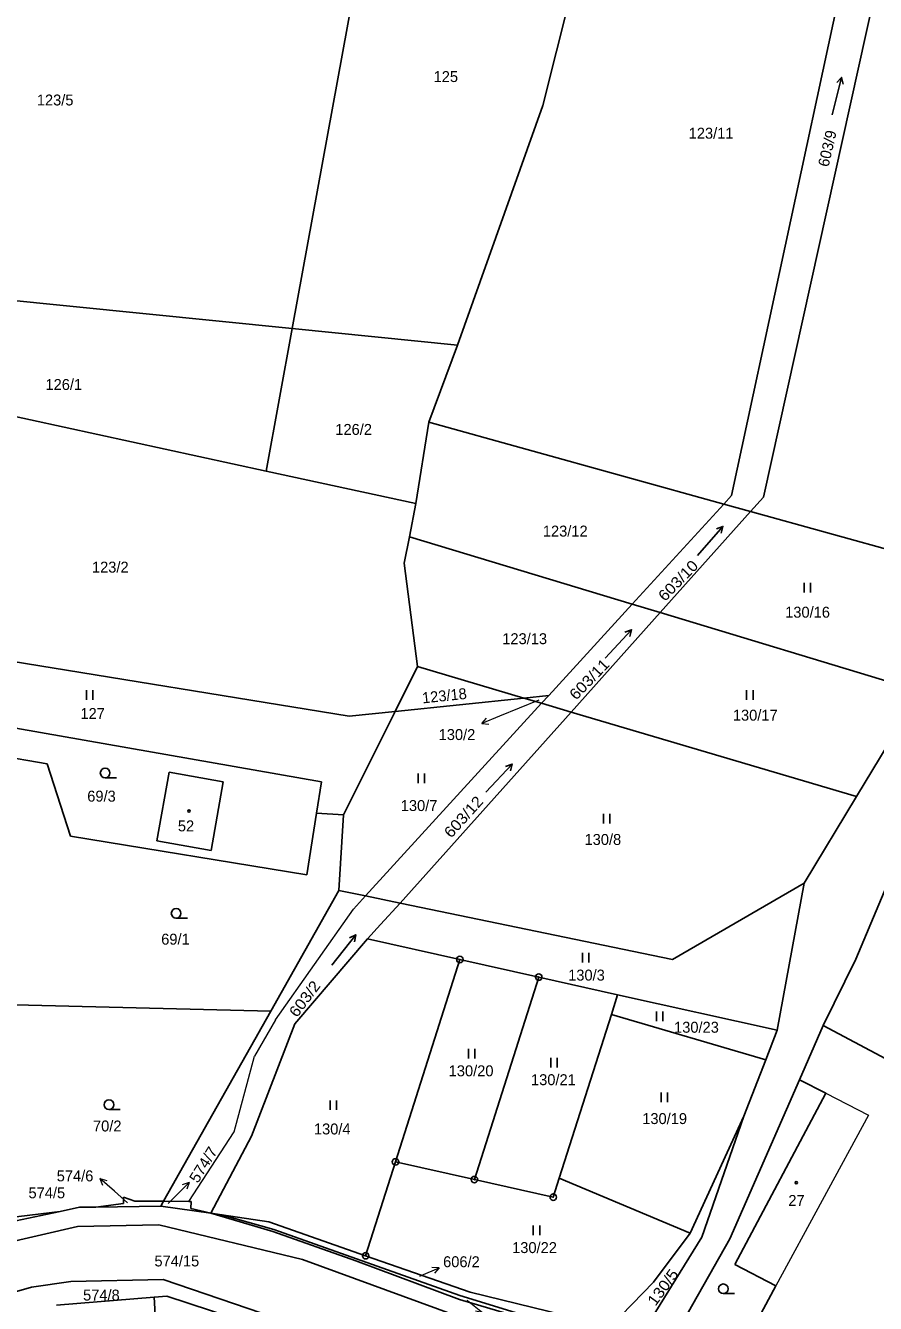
# Model space of a CAD drawing. Extents: x -664548 to -662415, y -1069720 to -1068208.
# Drawn here: x -663625.9 to -663493.9, y -1068905.8 to -1068707.2 of the extents above; entities that cross this region are included whole.
import ezdxf
from ezdxf.enums import TextEntityAlignment as Align

# ---------------------------------------------------------------- set-up
doc = ezdxf.new("R2010")
doc.units = 0
doc.header["$LTSCALE"] = 0.68
for name, color, linetype, lineweight in [('1', 7, 'Continuous', 25), ('3', 7, 'Continuous', 25), ('4', 7, 'Continuous', 13), ('5', 7, 'Continuous', 25), ('7', 7, 'Continuous', 13), ('8', 7, 'Continuous', 25)]:
    doc.layers.add(name, color=color, linetype=linetype, lineweight=lineweight)
doc.layers.add('2', color=7, linetype='Continuous')

msp = doc.modelspace()

# ---------------------------------------------------------------- linework, layer by layer
at = {"layer": '1'}
for p, q in [((-663545.54, -1068719.64), (-663534.68, -1068676.07)), ((-663574.64, -1068700.41), (-663584.45, -1068754.3)), ((-663516.25, -1068780.25), (-663499.18, -1068700.75)), ((-663511.29, -1068780.48), (-663493.94, -1068701.92)), ((-663558.79, -1068756.87), (-663545.54, -1068719.64)), ((-663661.19, -1068746.6), (-663584.45, -1068754.3)), ((-663584.45, -1068754.3), (-663588.49, -1068776.46)), ((-663584.45, -1068754.3), (-663558.79, -1068756.87)), ((-663563.23, -1068768.86), (-663558.79, -1068756.87)), ((-663652.43, -1068762.58), (-663588.49, -1068776.46)), ((-663565.25, -1068781.51), (-663563.23, -1068768.86)), ((-663517.45, -1068781.57), (-663563.23, -1068768.86)), ((-663588.49, -1068776.46), (-663565.25, -1068781.51)), ((-663565.25, -1068781.51), (-663566.26, -1068786.68)), ((-663531.67, -1068797.14), (-663517.45, -1068781.57)), ((-663517.45, -1068781.57), (-663516.25, -1068780.25)), ((-663513.3, -1068782.72), (-663517.45, -1068781.57)), ((-663513.3, -1068782.72), (-663511.29, -1068780.48)), ((-663527.36, -1068798.44), (-663513.3, -1068782.72)), ((-663482.4, -1068791.3), (-663513.3, -1068782.72)), ((-663566.26, -1068786.68), (-663567.06, -1068790.77)), ((-663531.67, -1068797.14), (-663566.26, -1068786.68)), ((-663567.06, -1068790.77), (-663565.01, -1068806.82)), ((-663544.62, -1068811.3), (-663531.67, -1068797.14)), ((-663527.36, -1068798.44), (-663531.67, -1068797.14)), ((-663541.17, -1068813.89), (-663527.36, -1068798.44)), ((-663487, -1068810.65), (-663527.36, -1068798.44)), ((-663575.64, -1068814.55), (-663662.01, -1068800.49)), ((-663568.49, -1068813.8), (-663565.01, -1068806.82)), ((-663565.01, -1068806.82), (-663548.52, -1068811.71)), ((-663664.51, -1068809.88), (-663579.92, -1068824.71)), ((-663548.52, -1068811.71), (-663544.62, -1068811.3)), ((-663545.75, -1068812.53), (-663544.62, -1068811.3)), ((-663496.86, -1068827.02), (-663487, -1068810.65)), ((-663573.08, -1068842.46), (-663545.75, -1068812.53)), ((-663568.49, -1068813.8), (-663548.52, -1068811.71)), ((-663548.52, -1068811.71), (-663545.75, -1068812.53)), ((-663545.75, -1068812.53), (-663541.17, -1068813.89)), ((-663576.48, -1068829.84), (-663568.49, -1068813.8)), ((-663575.64, -1068814.55), (-663568.49, -1068813.8)), ((-663567.72, -1068843.57), (-663541.17, -1068813.89)), ((-663541.17, -1068813.89), (-663496.86, -1068827.02)), ((-663633.27, -1068820.06), (-663622.49, -1068821.94)), ((-663622.49, -1068821.94), (-663618.9, -1068833.16)), ((-663603.54, -1068823.22), (-663605.47, -1068833.92)), ((-663603.54, -1068823.22), (-663595.2, -1068824.73)), ((-663595.2, -1068824.73), (-663597.06, -1068835.38)), ((-663580.69, -1068829.62), (-663579.92, -1068824.71)), ((-663504.97, -1068840.49), (-663496.86, -1068827.02)), ((-663582.19, -1068839.2), (-663580.69, -1068829.62)), ((-663576.48, -1068829.84), (-663580.69, -1068829.62)), ((-663576.48, -1068829.84), (-663577.21, -1068841.61)), ((-663496.98, -1068852.29), (-663487.98, -1068830.84)), ((-663582.19, -1068839.2), (-663618.9, -1068833.16)), ((-663605.47, -1068833.92), (-663597.06, -1068835.38)), ((-663504.97, -1068840.49), (-663525.44, -1068852.33)), ((-663509.16, -1068863.33), (-663504.97, -1068840.49)), ((-663577.21, -1068841.61), (-663587.78, -1068860.36)), ((-663573.08, -1068842.46), (-663577.21, -1068841.61)), ((-663567.72, -1068843.57), (-663573.08, -1068842.46)), ((-663567.72, -1068843.57), (-663570.78, -1068846.88)), ((-663525.44, -1068852.33), (-663567.72, -1068843.57)), ((-663570.78, -1068846.88), (-663572.77, -1068849.13)), ((-663584.08, -1068862.34), (-663572.77, -1068849.13)), ((-663572.77, -1068849.13), (-663558.43, -1068852.33)), ((-663558.43, -1068852.33), (-663568.43, -1068883.78)), ((-663558.43, -1068852.33), (-663546.19, -1068855.06)), ((-663502.03, -1068862.59), (-663496.98, -1068852.29)), ((-663556.18, -1068886.52), (-663546.19, -1068855.06)), ((-663546.19, -1068855.06), (-663533.94, -1068857.8)), ((-663533.94, -1068857.8), (-663534.91, -1068860.85)), ((-663533.94, -1068857.8), (-663509.16, -1068863.33)), ((-663587.78, -1068860.36), (-663629.6, -1068859.31)), ((-663587.78, -1068860.36), (-663604.44, -1068889.89)), ((-663534.91, -1068860.85), (-663543, -1068886.31)), ((-663534.91, -1068860.85), (-663510.95, -1068867.91)), ((-663590.78, -1068879.8), (-663584.08, -1068862.34)), ((-663505.71, -1068871.01), (-663502.03, -1068862.59)), ((-663502.03, -1068862.59), (-663489.86, -1068869.05)), ((-663509.16, -1068863.33), (-663510.95, -1068867.91)), ((-663510.95, -1068867.91), (-663514.37, -1068876.66)), ((-663516.53, -1068895.71), (-663505.71, -1068871.01)), ((-663505.71, -1068871.01), (-663501.63, -1068873.11)), ((-663515.74, -1068899.69), (-663501.63, -1068873.11)), ((-663514.37, -1068876.66), (-663522.67, -1068894.83)), ((-663514.37, -1068876.66), (-663520.89, -1068895.47)), ((-663590.78, -1068879.8), (-663597.1, -1068891.74)), ((-663568.43, -1068883.78), (-663573.06, -1068898.35)), ((-663568.43, -1068883.78), (-663556.18, -1068886.52)), ((-663556.18, -1068886.52), (-663543.93, -1068889.25)), ((-663543.93, -1068889.25), (-663543, -1068886.31)), ((-663543, -1068886.31), (-663522.67, -1068894.83)), ((-663617.47, -1068890.82), (-663614.93, -1068890.78)), ((-663614.93, -1068890.78), (-663610.65, -1068890.26)), ((-663614.93, -1068890.78), (-663604.85, -1068890.64)), ((-663610.65, -1068890.26), (-663610.64, -1068889.27)), ((-663608.87, -1068889.85), (-663610.64, -1068889.27)), ((-663608.87, -1068889.85), (-663604.44, -1068889.89)), ((-663604.85, -1068890.64), (-663604.44, -1068889.89)), ((-663604.85, -1068890.64), (-663597.1, -1068891.74)), ((-663604.44, -1068889.89), (-663600.52, -1068889.93)), ((-663600.52, -1068889.93), (-663600.17, -1068889.93)), ((-663600.18, -1068891.03), (-663600.17, -1068889.93)), ((-663630.55, -1068893.61), (-663620.46, -1068891.46)), ((-663630.52, -1068892.69), (-663620.46, -1068891.46)), ((-663620.46, -1068891.46), (-663617.47, -1068890.82)), ((-663597.1, -1068891.74), (-663600.18, -1068891.03)), ((-663597.1, -1068891.74), (-663595.38, -1068892)), ((-663587.49, -1068894.61), (-663597.1, -1068891.74)), ((-663587.29, -1068894.28), (-663595.38, -1068892)), ((-663595.38, -1068892), (-663588.08, -1068893.1)), ((-663617.82, -1068893.8), (-663649.76, -1068901.16)), ((-663605.19, -1068893.57), (-663617.82, -1068893.8)), ((-663582.88, -1068898.95), (-663605.19, -1068893.57)), ((-663588.08, -1068893.1), (-663573.06, -1068898.35)), ((-663574.57, -1068899.16), (-663587.49, -1068894.61)), ((-663558.43, -1068904.54), (-663587.29, -1068894.28)), ((-663520.89, -1068895.47), (-663530.21, -1068910.52)), ((-663522.67, -1068894.83), (-663528.37, -1068902.45)), ((-663524.71, -1068910.19), (-663516.53, -1068895.71)), ((-663573.06, -1068898.35), (-663556.86, -1068904.01)), ((-663559.19, -1068907.57), (-663582.88, -1068898.95)), ((-663558.5, -1068905.16), (-663574.57, -1068899.16)), ((-663509.37, -1068903.03), (-663515.74, -1068899.69)), ((-663624.91, -1068903.24), (-663618.82, -1068902.34)), ((-663618.82, -1068902.34), (-663604.5, -1068902.02)), ((-663604.5, -1068902.02), (-663577.56, -1068911.22)), ((-663528.37, -1068902.45), (-663535.07, -1068909.34)), ((-663635.63, -1068906.27), (-663624.91, -1068903.24)), ((-663605.87, -1068904.77), (-663603.93, -1068904.61)), ((-663603.93, -1068904.61), (-663578.31, -1068913.03)), ((-663558.43, -1068904.54), (-663544.45, -1068908.84)), ((-663556.86, -1068904.01), (-663535.07, -1068909.34)), ((-663512.86, -1068909.48), (-663509.37, -1068903.03)), ((-663621.07, -1068906.02), (-663605.87, -1068904.77)), ((-663605.41, -1068914.1), (-663605.87, -1068904.77)), ((-663545.38, -1068909.05), (-663558.5, -1068905.16))]:
    msp.add_line(p, q, dxfattribs=at)
at = {"layer": '3'}
for p, q in [((-663499.172, -1068715.285), (-663498.922, -1068716.354)), ((-663517.584, -1068785.039), (-663517.847, -1068786.105)), ((-663504.981, -1068795.33), (-663504.981, -1068793.83)), ((-663503.98, -1068795.33), (-663503.98, -1068793.83)), ((-663531.766, -1068801.109), (-663532.066, -1068802.166)), ((-663616.421, -1068811.99), (-663616.421, -1068810.49)), ((-663615.42, -1068811.99), (-663615.42, -1068810.49)), ((-663513.911, -1068812), (-663513.911, -1068810.5)), ((-663512.91, -1068812), (-663512.91, -1068810.5)), ((-663550.296, -1068821.959), (-663550.596, -1068823.016)), ((-663613.503, -1068824.1), (-663611.753, -1068824.1)), ((-663564.931, -1068824.96), (-663564.931, -1068823.46)), ((-663563.93, -1068824.96), (-663563.93, -1068823.46)), ((-663536.141, -1068831.18), (-663536.141, -1068829.68)), ((-663535.14, -1068831.18), (-663535.14, -1068829.68)), ((-663602.483, -1068845.91), (-663600.733, -1068845.91)), ((-663574.596, -1068848.498), (-663574.802, -1068849.576)), ((-663539.421, -1068852.79), (-663539.421, -1068851.29)), ((-663538.42, -1068852.79), (-663538.42, -1068851.29)), ((-663527.911, -1068861.92), (-663527.911, -1068860.42)), ((-663526.91, -1068861.92), (-663526.91, -1068860.42)), ((-663557.101, -1068867.71), (-663557.101, -1068866.21)), ((-663556.1, -1068867.71), (-663556.1, -1068866.21)), ((-663544.321, -1068869.09), (-663544.321, -1068867.59)), ((-663543.32, -1068869.09), (-663543.32, -1068867.59)), ((-663578.581, -1068875.71), (-663578.581, -1068874.21)), ((-663577.58, -1068875.71), (-663577.58, -1068874.21)), ((-663527.181, -1068874.49), (-663527.181, -1068872.99)), ((-663526.18, -1068874.49), (-663526.18, -1068872.99)), ((-663612.913, -1068875.64), (-663611.163, -1068875.64)), ((-663547.041, -1068895.17), (-663547.041, -1068893.67)), ((-663546.04, -1068895.17), (-663546.04, -1068893.67)), ((-663517.543, -1068904.24), (-663515.793, -1068904.24))]:
    msp.add_line(p, q, dxfattribs=at)
for points in [[(-663500.623, -1068721.106), (-663499.172, -1068715.285), (-663499.895, -1068716.111)], [(-663521.52, -1068789.567), (-663517.584, -1068785.039), (-663518.604, -1068785.447)], [(-663535.858, -1068805.497), (-663531.766, -1068801.109), (-663532.799, -1068801.482)], [(-663554.388, -1068826.347), (-663550.296, -1068821.959), (-663551.329, -1068822.332)], [(-663578.29, -1068853.226), (-663574.596, -1068848.498), (-663575.592, -1068848.959)]]:
    msp.add_lwpolyline(points, dxfattribs=at)
for centre in [(-663613.5029, -1068823.3498), (-663602.4829, -1068845.1598), (-663612.9129, -1068874.8898), (-663517.5429, -1068903.4898)]:
    msp.add_circle(centre, 0.75, dxfattribs=at)
at = {"layer": '4'}
for p, q in [((-663574.94, -1068844.5), (-663573.08, -1068842.46)), ((-663587.07, -1068861.7), (-663574.94, -1068844.5)), ((-663587.07, -1068861.7), (-663590.32, -1068867.36)), ((-663593.48, -1068879.11), (-663590.32, -1068867.36)), ((-663501.63, -1068873.11), (-663495.02, -1068876.51)), ((-663495.02, -1068876.51), (-663509.37, -1068903.03)), ((-663600.52, -1068889.93), (-663593.48, -1068879.11))]:
    msp.add_line(p, q, dxfattribs=at)
at = {"layer": '5'}
for centre in [(-663600.4868, -1068829.2692), (-663506.2168, -1068886.9992)]:
    msp.add_circle(centre, 0.175, dxfattribs=at)
at = {"layer": '7'}
for p, q in [((-663555.042, -1068815.664), (-663553.926, -1068815.753)), ((-663614.335, -1068886.371), (-663613.908, -1068887.406)), ((-663600.468, -1068886.968), (-663601.53, -1068887.322)), ((-663561.668, -1068900.227), (-663562.785, -1068900.158))]:
    msp.add_line(p, q, dxfattribs=at)
for points in [[(-663546.19, -1068812.06), (-663552.26, -1068814.54), (-663555.042, -1068815.664), (-663554.302, -1068814.825)], [(-663610.04, -1068890.12), (-663612.07, -1068888.34), (-663614.335, -1068886.371), (-663613.251, -1068886.65)], [(-663603.72, -1068890.24), (-663602.59, -1068889.09), (-663600.468, -1068886.968), (-663600.822, -1068888.03)], [(-663564.65, -1068901.5), (-663564.43, -1068901.4), (-663561.668, -1068900.227), (-663562.394, -1068901.08)], [(-663557.35, -1068905.23), (-663557.26, -1068905.29), (-663554.928, -1068907.179), (-663556.021, -1068906.937)]]:
    msp.add_lwpolyline(points, dxfattribs=at)
at = {"layer": '8'}
for centre, radius in [((-663558.43, -1068852.3299), 0.5), ((-663558.43, -1068852.3299), 0.0303), ((-663546.19, -1068855.0599), 0.5), ((-663546.19, -1068855.0599), 0.0303), ((-663568.43, -1068883.7799), 0.5), ((-663568.43, -1068883.7799), 0.0303), ((-663556.18, -1068886.5199), 0.5), ((-663556.18, -1068886.5199), 0.0303), ((-663543.93, -1068889.2499), 0.5), ((-663543.93, -1068889.2499), 0.0303), ((-663573.06, -1068898.3499), 0.5), ((-663573.06, -1068898.3499), 0.0303)]:
    msp.add_circle(centre, radius, dxfattribs=at)

# ---------------------------------------------------------------- texts
at = {"layer": '2'}
for s, p in [('125', (-663562.51, -1068716.015)), ('123/5', (-663624.11, -1068719.655)), ('123/11', (-663522.91, -1068724.814)), ('126/1', (-663622.77, -1068763.854)), ('126/2', (-663577.77, -1068770.834)), ('123/12', (-663545.55, -1068786.625)), ('123/2', (-663615.55, -1068792.225)), ('130/16', (-663507.93, -1068799.225)), ('123/13', (-663551.85, -1068803.344)), ('127', (-663617.34, -1068814.965)), ('130/17', (-663516.05, -1068815.225)), ('69/3', (-663616.28, -1068827.804)), ('130/7', (-663567.61, -1068829.265)), ('52', (-663602.21, -1068832.425)), ('130/8', (-663539.08, -1068834.535)), ('69/1', (-663604.8, -1068850.025)), ('130/3', (-663541.62, -1068855.604)), ('130/23', (-663525.18, -1068863.705)), ('130/20', (-663560.17, -1068870.475)), ('130/21', (-663547.39, -1068871.854)), ('130/19', (-663530.12, -1068877.895)), ('70/2', (-663615.39, -1068879.045)), ('130/4', (-663581.09, -1068879.505)), ('574/5', (-663625.4, -1068889.425)), ('27', (-663507.44, -1068890.615)), ('130/22', (-663550.32, -1068897.935)), ('574/15', (-663605.85, -1068900.015)), ('574/8', (-663616.93, -1068905.314))]:
    msp.add_text(s, height=1.7, dxfattribs=at).set_placement(p)
for s, rotation, p in [('603/9', 77, (-663501.205, -1068729.295)), ('123/18', 6, (-663564.205, -1068812.552))]:
    msp.add_text(s, height=1.7, rotation=rotation, dxfattribs=at).set_placement(p)
for s, rotation, width, p in [('603/10', 46, 1.1, (-663526.594, -1068796.805)), ('603/11', 46, 1.1, (-663540.384, -1068812.135)), ('603/12', 48, 1.1, (-663559.794, -1068833.574)), ('603/2', 53, 1.1, (-663583.73, -1068861.445)), ('574/7', 58, 1.05, (-663599.119, -1068887.185)), ('130/5', 54, 1.1, (-663528.066, -1068906.279))]:
    msp.add_text(s, height=1.7, rotation=rotation, dxfattribs=dict(at, width=width)).set_placement(p)
for s, p in [('130/2', (-663556.04, -1068818.235)), ('574/6', (-663615.33, -1068886.795))]:
    msp.add_text(s, height=1.7, dxfattribs=at).set_placement(p, align=Align.RIGHT)
msp.add_text('606/2', height=1.7, dxfattribs=at).set_placement((-663558.19, -1068900.135), align=Align.CENTER)

doc.saveas('drawing.dxf')
